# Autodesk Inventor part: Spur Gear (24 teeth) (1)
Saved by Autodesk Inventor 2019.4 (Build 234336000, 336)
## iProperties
Created: 2020-02
Part Number: Spur Gear (24 teeth) (1)
Material: Generic
Description: Spur Gear; Module: 1.0; Num Teeth: 24; Pressure Angle: 20.0; Backlash: 0.00 mm
Document SubType Name: Modeling
Designer: Administrator
Density: 1 g/cm^3
Appearance: Default
Title: Spur Gear (24 teeth) (1)
Author: Administrator
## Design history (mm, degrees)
feature "Body1"
body "Solid1"
